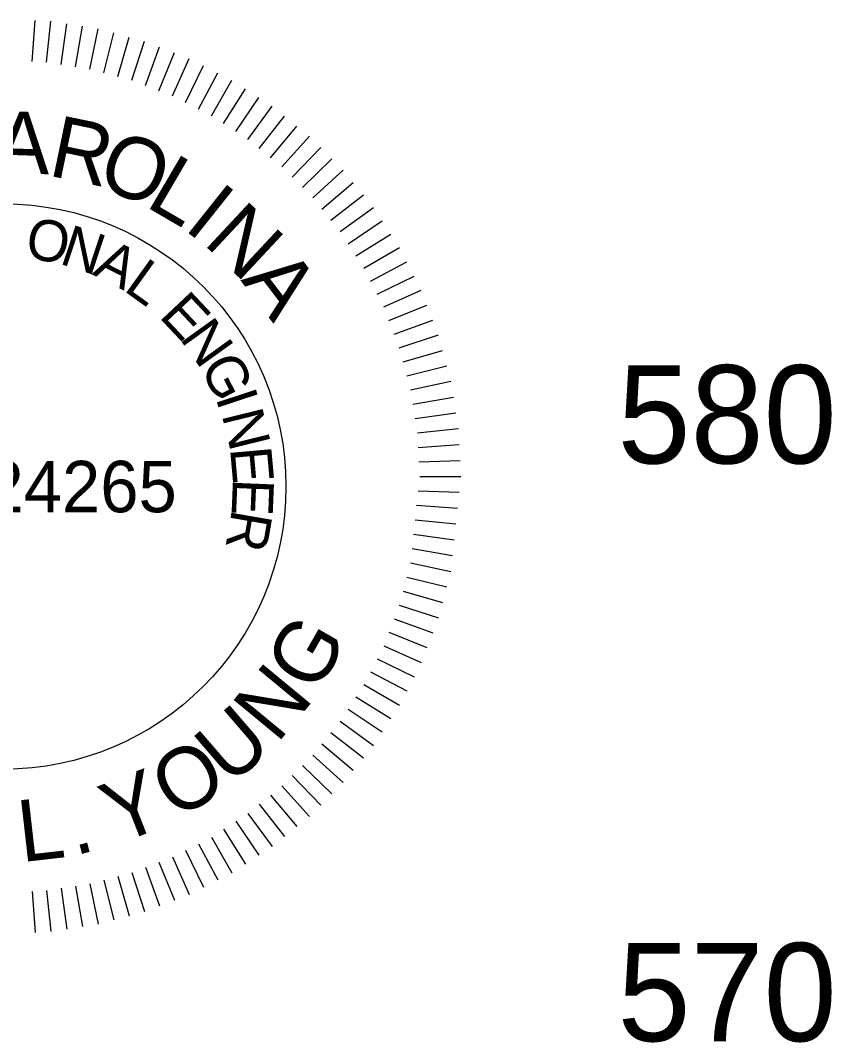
# Model space of a CAD drawing. Extents: x 1964377 to 1966966, y 1116414 to 1123213.
# Drawn here: x 1966072.9 to 1966143.1, y 1122576.7 to 1122665.1 of the extents above; entities that cross this region are included whole.
import ezdxf

# ---------------------------------------------------------------- set-up
doc = ezdxf.new("R2010")
doc.units = 0
doc.layers.add('RD_DDB_Profile_Elev', color=7, linetype='Continuous')
doc.layers.add('RD_TX_PEShield', color=7, linetype='Continuous')

msp = doc.modelspace()

# ---------------------------------------------------------------- linework, layer by layer
at = {"layer": 'RD_TX_PEShield'}
for p, q in [((1966073.958, 1122661.589), (1966074.206, 1122665.136)), ((1966073.958, 1122661.589), (1966074.206, 1122665.136)), ((1966075.214, 1122661.523), (1966075.587, 1122665.063)), ((1966075.214, 1122661.523), (1966075.587, 1122665.063)), ((1966076.457, 1122661.326), (1966076.952, 1122664.847)), ((1966076.457, 1122661.326), (1966076.952, 1122664.847)), ((1966077.698, 1122661.13), (1966078.316, 1122664.631)), ((1966077.698, 1122661.13), (1966078.316, 1122664.631)), ((1966078.941, 1122660.933), (1966079.681, 1122664.415)), ((1966078.941, 1122660.933), (1966079.681, 1122664.415)), ((1966078.941, 1122660.933), (1966079.681, 1122664.415)), ((1966080.156, 1122660.607), (1966081.016, 1122664.057)), ((1966080.156, 1122660.607), (1966081.016, 1122664.057)), ((1966080.156, 1122660.607), (1966081.016, 1122664.057)), ((1966081.37, 1122660.282), (1966082.35, 1122663.7)), ((1966081.37, 1122660.282), (1966082.35, 1122663.7)), ((1966081.37, 1122660.282), (1966082.35, 1122663.7)), ((1966082.585, 1122659.956), (1966083.685, 1122663.342)), ((1966082.585, 1122659.956), (1966083.685, 1122663.342)), ((1966082.585, 1122659.956), (1966083.685, 1122663.342)), ((1966083.76, 1122659.505), (1966084.976, 1122662.847)), ((1966083.76, 1122659.505), (1966084.976, 1122662.847)), ((1966083.76, 1122659.505), (1966084.976, 1122662.847)), ((1966084.933, 1122659.055), (1966086.265, 1122662.352)), ((1966084.933, 1122659.055), (1966086.265, 1122662.352)), ((1966084.933, 1122659.055), (1966086.265, 1122662.352)), ((1966086.108, 1122658.604), (1966087.556, 1122661.856)), ((1966086.108, 1122658.604), (1966087.556, 1122661.856)), ((1966086.108, 1122658.604), (1966087.556, 1122661.856)), ((1966087.229, 1122658.033), (1966088.787, 1122661.229)), ((1966087.229, 1122658.033), (1966088.787, 1122661.229)), ((1966087.229, 1122658.033), (1966088.787, 1122661.229)), ((1966088.348, 1122657.462), (1966090.018, 1122660.602)), ((1966088.348, 1122657.462), (1966090.018, 1122660.602)), ((1966088.348, 1122657.462), (1966090.018, 1122660.602)), ((1966089.469, 1122656.891), (1966091.249, 1122659.974)), ((1966089.469, 1122656.891), (1966091.249, 1122659.974)), ((1966089.469, 1122656.891), (1966091.249, 1122659.974)), ((1966090.524, 1122656.206), (1966092.409, 1122659.221)), ((1966090.524, 1122656.206), (1966092.409, 1122659.221)), ((1966090.524, 1122656.206), (1966092.409, 1122659.221)), ((1966091.578, 1122655.522), (1966093.567, 1122658.469)), ((1966091.578, 1122655.522), (1966093.567, 1122658.469)), ((1966091.578, 1122655.522), (1966093.567, 1122658.469)), ((1966092.633, 1122654.836), (1966094.726, 1122657.717)), ((1966092.633, 1122654.836), (1966094.726, 1122657.717)), ((1966092.633, 1122654.836), (1966094.726, 1122657.717)), ((1966093.611, 1122654.045), (1966095.8, 1122656.847)), ((1966093.611, 1122654.045), (1966095.8, 1122656.847)), ((1966093.611, 1122654.045), (1966095.8, 1122656.847)), ((1966094.588, 1122653.254), (1966096.873, 1122655.978)), ((1966094.588, 1122653.254), (1966096.873, 1122655.978)), ((1966094.588, 1122653.254), (1966096.873, 1122655.978)), ((1966095.566, 1122652.462), (1966097.948, 1122655.108)), ((1966095.566, 1122652.462), (1966097.948, 1122655.108)), ((1966095.566, 1122652.462), (1966097.948, 1122655.108)), ((1966096.455, 1122651.572), (1966098.925, 1122654.13)), ((1966096.455, 1122651.572), (1966098.925, 1122654.13)), ((1966096.455, 1122651.572), (1966098.925, 1122654.13)), ((1966097.344, 1122650.684), (1966099.901, 1122653.154)), ((1966097.344, 1122650.684), (1966099.901, 1122653.154)), ((1966097.344, 1122650.684), (1966099.901, 1122653.154)), ((1966098.233, 1122649.794), (1966100.879, 1122652.176)), ((1966098.233, 1122649.794), (1966100.879, 1122652.176)), ((1966098.233, 1122649.794), (1966100.879, 1122652.176)), ((1966099.025, 1122648.816), (1966101.749, 1122651.102)), ((1966099.025, 1122648.816), (1966101.749, 1122651.102)), ((1966099.025, 1122648.816), (1966101.749, 1122651.102)), ((1966099.816, 1122647.84), (1966102.618, 1122650.029)), ((1966099.816, 1122647.84), (1966102.618, 1122650.029)), ((1966099.816, 1122647.84), (1966102.618, 1122650.029)), ((1966100.608, 1122646.862), (1966103.488, 1122648.955)), ((1966100.608, 1122646.862), (1966103.488, 1122648.955)), ((1966100.608, 1122646.862), (1966103.488, 1122648.955)), ((1966101.293, 1122645.807), (1966104.241, 1122647.795)), ((1966101.293, 1122645.807), (1966104.241, 1122647.795)), ((1966101.293, 1122645.807), (1966104.241, 1122647.795)), ((1966101.977, 1122644.753), (1966104.993, 1122646.637)), ((1966101.977, 1122644.753), (1966104.993, 1122646.637)), ((1966101.977, 1122644.753), (1966104.993, 1122646.637)), ((1966102.663, 1122643.698), (1966105.746, 1122645.478)), ((1966102.663, 1122643.698), (1966105.746, 1122645.478)), ((1966102.663, 1122643.698), (1966105.746, 1122645.478)), ((1966103.234, 1122642.577), (1966106.373, 1122644.246)), ((1966103.234, 1122642.577), (1966106.373, 1122644.246)), ((1966103.234, 1122642.577), (1966106.373, 1122644.246)), ((1966103.804, 1122641.457), (1966107, 1122643.016)), ((1966103.804, 1122641.457), (1966107, 1122643.016)), ((1966103.804, 1122641.457), (1966107, 1122643.016)), ((1966104.376, 1122640.336), (1966107.628, 1122641.784)), ((1966104.376, 1122640.336), (1966107.628, 1122641.784)), ((1966104.376, 1122640.336), (1966107.628, 1122641.784)), ((1966104.826, 1122639.162), (1966108.123, 1122640.494)), ((1966104.826, 1122639.162), (1966108.123, 1122640.494)), ((1966104.826, 1122639.162), (1966108.123, 1122640.494)), ((1966105.277, 1122637.989), (1966108.618, 1122639.205)), ((1966105.277, 1122637.989), (1966108.618, 1122639.205)), ((1966105.277, 1122637.989), (1966108.618, 1122639.205)), ((1966105.728, 1122636.814), (1966109.113, 1122637.914)), ((1966105.728, 1122636.814), (1966109.113, 1122637.914)), ((1966105.728, 1122636.814), (1966109.113, 1122637.914)), ((1966106.053, 1122635.599), (1966109.471, 1122636.579)), ((1966106.053, 1122635.599), (1966109.471, 1122636.579)), ((1966106.053, 1122635.599), (1966109.471, 1122636.579)), ((1966106.378, 1122634.385), (1966109.828, 1122635.245)), ((1966106.378, 1122634.385), (1966109.828, 1122635.245)), ((1966106.378, 1122634.385), (1966109.828, 1122635.245)), ((1966106.704, 1122633.17), (1966110.186, 1122633.91)), ((1966106.704, 1122633.17), (1966110.186, 1122633.91)), ((1966106.704, 1122633.17), (1966110.186, 1122633.91)), ((1966106.901, 1122631.927), (1966110.403, 1122632.544)), ((1966106.901, 1122631.927), (1966110.403, 1122632.544)), ((1966106.901, 1122631.927), (1966110.403, 1122632.544)), ((1966107.097, 1122630.686), (1966110.619, 1122631.181)), ((1966107.097, 1122630.686), (1966110.619, 1122631.181)), ((1966107.097, 1122630.686), (1966110.619, 1122631.181)), ((1966107.294, 1122629.443), (1966110.835, 1122629.815)), ((1966107.294, 1122629.443), (1966110.835, 1122629.815)), ((1966107.294, 1122629.443), (1966110.835, 1122629.815)), ((1966107.36, 1122628.187), (1966110.907, 1122628.435)), ((1966107.36, 1122628.187), (1966110.907, 1122628.435)), ((1966107.36, 1122628.187), (1966110.907, 1122628.435)), ((1966107.426, 1122626.932), (1966110.979, 1122627.056)), ((1966107.426, 1122626.932), (1966110.979, 1122627.056)), ((1966107.426, 1122626.932), (1966110.979, 1122627.056)), ((1966107.492, 1122625.675), (1966111.052, 1122625.675)), ((1966107.492, 1122625.675), (1966111.052, 1122625.675)), ((1966107.492, 1122625.675), (1966111.052, 1122625.675)), ((1966107.36, 1122624.421), (1966110.907, 1122624.297)), ((1966107.36, 1122624.421), (1966110.907, 1122624.297)), ((1966107.229, 1122623.173), (1966110.763, 1122622.926)), ((1966107.229, 1122623.173), (1966110.763, 1122622.926)), ((1966107.098, 1122621.928), (1966110.619, 1122621.558)), ((1966107.098, 1122621.928), (1966110.619, 1122621.558)), ((1966106.967, 1122620.683), (1966110.475, 1122620.19)), ((1966106.967, 1122620.683), (1966110.475, 1122620.19)), ((1966106.836, 1122619.435), (1966110.331, 1122618.819)), ((1966106.836, 1122619.435), (1966110.331, 1122618.819)), ((1966106.704, 1122618.181), (1966110.186, 1122617.441)), ((1966106.704, 1122618.181), (1966110.186, 1122617.441)), ((1966106.378, 1122616.966), (1966109.828, 1122616.106)), ((1966106.378, 1122616.966), (1966109.828, 1122616.106)), ((1966106.053, 1122615.752), (1966109.471, 1122614.772)), ((1966106.053, 1122615.752), (1966109.471, 1122614.772)), ((1966105.728, 1122614.537), (1966109.113, 1122613.437)), ((1966105.728, 1122614.537), (1966109.113, 1122613.437)), ((1966105.277, 1122613.362), (1966108.618, 1122612.146)), ((1966105.277, 1122613.362), (1966108.618, 1122612.146)), ((1966104.826, 1122612.189), (1966108.123, 1122610.857)), ((1966104.826, 1122612.189), (1966108.123, 1122610.857)), ((1966104.376, 1122611.015), (1966107.628, 1122609.567)), ((1966104.376, 1122611.015), (1966107.628, 1122609.567)), ((1966103.804, 1122609.894), (1966107, 1122608.335)), ((1966103.804, 1122609.894), (1966107, 1122608.335)), ((1966103.234, 1122608.774), (1966106.373, 1122607.105)), ((1966103.234, 1122608.774), (1966106.373, 1122607.105)), ((1966102.663, 1122607.653), (1966105.746, 1122605.873)), ((1966102.663, 1122607.653), (1966105.746, 1122605.873)), ((1966101.977, 1122606.598), (1966104.993, 1122604.714)), ((1966101.977, 1122606.598), (1966104.993, 1122604.714)), ((1966101.293, 1122605.544), (1966104.241, 1122603.556)), ((1966101.293, 1122605.544), (1966104.241, 1122603.556)), ((1966100.608, 1122604.489), (1966103.488, 1122602.396)), ((1966100.608, 1122604.489), (1966103.488, 1122602.396)), ((1966099.816, 1122603.511), (1966102.618, 1122601.322)), ((1966099.816, 1122603.511), (1966102.618, 1122601.322)), ((1966099.025, 1122602.534), (1966101.749, 1122600.249)), ((1966099.025, 1122602.534), (1966101.749, 1122600.249)), ((1966098.233, 1122601.557), (1966100.879, 1122599.175)), ((1966098.233, 1122601.557), (1966100.879, 1122599.175)), ((1966097.344, 1122600.667), (1966099.901, 1122598.197)), ((1966097.344, 1122600.667), (1966099.901, 1122598.197)), ((1966096.455, 1122599.778), (1966098.925, 1122597.221)), ((1966096.455, 1122599.778), (1966098.925, 1122597.221)), ((1966095.566, 1122598.889), (1966097.948, 1122596.243)), ((1966094.588, 1122598.097), (1966096.873, 1122595.373)), ((1966094.588, 1122598.097), (1966096.873, 1122595.373)), ((1966093.611, 1122597.306), (1966095.8, 1122594.504)), ((1966093.611, 1122597.306), (1966095.8, 1122594.504)), ((1966091.578, 1122595.829), (1966093.567, 1122592.881)), ((1966091.578, 1122595.829), (1966093.567, 1122592.881)), ((1966092.633, 1122596.514), (1966094.726, 1122593.634)), ((1966092.633, 1122596.514), (1966094.726, 1122593.634)), ((1966090.524, 1122595.145), (1966092.409, 1122592.129)), ((1966090.524, 1122595.145), (1966092.409, 1122592.129)), ((1966089.469, 1122594.46), (1966091.249, 1122591.376)), ((1966089.469, 1122594.46), (1966091.249, 1122591.376)), ((1966087.229, 1122593.318), (1966088.787, 1122590.122)), ((1966087.229, 1122593.318), (1966088.787, 1122590.122)), ((1966088.348, 1122593.888), (1966090.018, 1122590.749)), ((1966088.348, 1122593.888), (1966090.018, 1122590.749)), ((1966084.933, 1122592.296), (1966086.265, 1122588.999)), ((1966084.933, 1122592.296), (1966086.265, 1122588.999)), ((1966086.108, 1122592.747), (1966087.556, 1122589.494)), ((1966086.108, 1122592.747), (1966087.556, 1122589.494)), ((1966082.585, 1122591.395), (1966083.685, 1122588.009)), ((1966082.585, 1122591.395), (1966083.685, 1122588.009)), ((1966083.76, 1122591.845), (1966084.976, 1122588.504)), ((1966083.76, 1122591.845), (1966084.976, 1122588.504)), ((1966078.941, 1122590.418), (1966079.681, 1122586.936)), ((1966078.941, 1122590.418), (1966079.681, 1122586.936)), ((1966080.156, 1122590.744), (1966081.016, 1122587.294)), ((1966080.156, 1122590.744), (1966081.016, 1122587.294)), ((1966081.37, 1122591.069), (1966082.35, 1122587.651)), ((1966081.37, 1122591.069), (1966082.35, 1122587.651)), ((1966073.958, 1122589.762), (1966074.206, 1122586.215)), ((1966073.958, 1122589.762), (1966074.206, 1122586.215)), ((1966075.214, 1122589.828), (1966075.587, 1122586.287)), ((1966075.214, 1122589.828), (1966075.587, 1122586.287)), ((1966076.457, 1122590.025), (1966076.952, 1122586.504)), ((1966076.457, 1122590.025), (1966076.952, 1122586.504)), ((1966077.698, 1122590.221), (1966078.316, 1122586.72)), ((1966077.698, 1122590.221), (1966078.316, 1122586.72))]:
    msp.add_line(p, q, dxfattribs=at)
msp.add_circle((1966071.447, 1122624.797), 24.475, dxfattribs=at)

# ---------------------------------------------------------------- texts
at = {"layer": 'RD_DDB_Profile_Elev'}
for s, p in [('580', (1966124.607, 1122626.797)), ('570', (1966124.607, 1122576.797))]:
    msp.add_text(s, height=8.5, dxfattribs=at).set_placement(p)
at = {"layer": 'RD_TX_PEShield'}
for s, height, rotation, p in [('A', 5.34, 357.94482, (1966070.656, 1122651.988)), ('R', 5.34, 348.26699, (1966075.238, 1122651.734)), ('O', 5.34, 339.32858, (1966079.377, 1122650.818)), ('L', 5.34, 329.65075, (1966083.639, 1122649.114)), ('I', 5.34, 321.46627, (1966086.976, 1122647.131)), ('N', 5.34, 317.00069, (1966088.668, 1122645.854)), ('O', 3.56, 350.40454, (1966073.246, 1122644.622)), ('N', 3.56, 341.70291, (1966076.224, 1122644.122)), ('A', 3.56, 333.00129, (1966079.093, 1122643.176)), ('L', 3.56, 324.29966, (1966081.785, 1122641.808)), ('A', 5.34, 307.32286, (1966091.963, 1122642.659)), ('E', 3.56, 313.22511, (1966084.86, 1122639.505)), ('N', 3.56, 305.73175, (1966086.664, 1122637.63)), ('G', 3.56, 297.03012, (1966088.43, 1122635.18)), ('I', 3.56, 288.3285, (1966089.806, 1122632.492)), ('N', 3.56, 283.84405, (1966090.351, 1122631.033)), ('E', 3.56, 275.14243, (1966091.077, 1122628.101)), ('E', 3.56, 267.64906, (1966091.34, 1122625.513)), ('R', 3.56, 260.15569, (1966091.263, 1122622.912)), ('G', 5.34, 60.11131, (1966098.556, 1122606.774)), ('N', 5.34, 50.43348, (1966095.14, 1122602.473)), ('U', 5.34, 40.75564, (1966091.05, 1122598.808)), ('O', 5.34, 31.07781, (1966086.402, 1122595.882)), ('Y', 5.34, 21.39998, (1966081.328, 1122593.779)), ('L', 5.34, 6.51713, (1966073.03, 1122592.282)), ('.', 5.34, 14.70161, (1966077.643, 1122592.839))]:
    msp.add_text(s, height=height, rotation=rotation, dxfattribs=at).set_placement(p)
msp.add_text('NO. 24265', height=4.4501, dxfattribs=at).set_placement((1966057.693, 1122622.572))

doc.saveas('drawing.dxf')
